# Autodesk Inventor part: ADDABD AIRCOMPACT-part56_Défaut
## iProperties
Shininess: 64.0
Length Units: 11269
Angle Units: 11279
Time Units: 11290
Mass Units: 11283
Length Display Precision: 3
Angle Display Precision: 2
Compacted: True
Part Number: ADDABD AIRCOMPACT-part56_Défaut
Document SubType Name: Modeling
Created: 2006-01
Material: Par défaut
Designer: riri
Density: 0.0
Volumn: 0.0
Area: 0.0
PropertySet Name: Model Information
Control State: 0
Master: False
Checked Out: False
Author: riri
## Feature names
1. Base1
